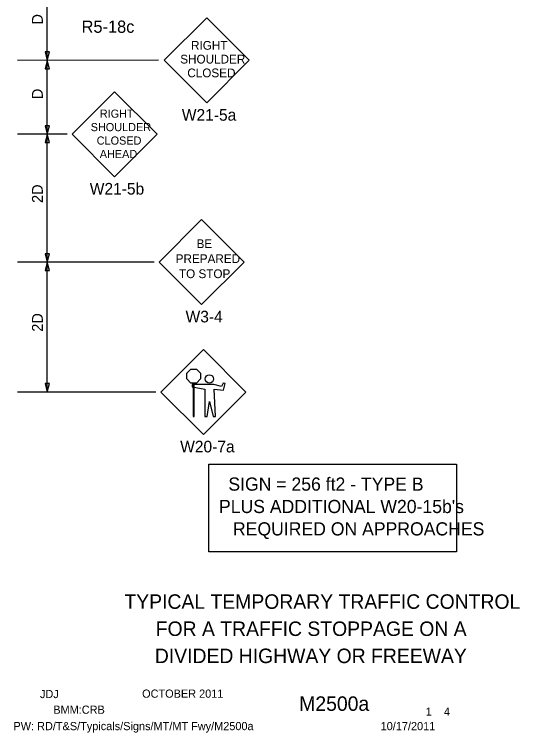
# Model space of a CAD drawing. Extents: x -1809 to 1554, y -1087 to 323.
# Drawn here: x -1380 to -996, y -949 to -403 of the extents above; entities that cross this region are included whole.
import ezdxf

# ---------------------------------------------------------------- set-up
doc = ezdxf.new("R2010")
doc.units = 0
for name, color, linetype in [('BORDER_SIGNAL_WO', 7, 'Continuous'), ('SCRATCH_LEVEL_C', 7, 'Continuous'), ('TRAFFIC_SIGNS_PR', 7, 'Continuous'), ('TYPICAL_TEXT_DIMEN_PR', 7, 'Continuous')]:
    doc.layers.add(name, color=color, linetype=linetype)

msp = doc.modelspace()

# ---------------------------------------------------------------- linework, layer by layer
at = {"layer": 'SCRATCH_LEVEL_C'}
msp.add_lwpolyline([(-1232.08, -744.7), (-1043.79, -744.7), (-1043.79, -811.2), (-1232.08, -811.2)], close=True, dxfattribs=at)
at = {"layer": 'TRAFFIC_SIGNS_PR'}
for p, q in [((-1233.59, -405.87), (-1265.83, -438.12)), ((-1201.35, -438.12), (-1233.59, -405.87)), ((-1265.83, -438.12), (-1233.59, -470.36)), ((-1233.59, -470.36), (-1201.35, -438.12)), ((-1303.55, -461.96), (-1335.79, -494.2)), ((-1271.3, -494.2), (-1303.55, -461.96)), ((-1335.79, -494.2), (-1303.55, -526.45)), ((-1303.55, -526.45), (-1271.3, -494.2)), ((-1237.46, -559.02), (-1269.7, -591.26)), ((-1205.21, -591.26), (-1237.46, -559.02)), ((-1269.7, -591.26), (-1237.46, -623.5)), ((-1237.46, -623.5), (-1205.21, -591.26)), ((-1236.11, -657.7), (-1268.35, -689.95)), ((-1203.86, -689.95), (-1236.11, -657.7)), ((-1268.35, -689.95), (-1236.11, -722.19)), ((-1236.11, -722.19), (-1203.86, -689.95))]:
    msp.add_line(p, q, dxfattribs=at)
for points in [[(-1245.65, -672.57), (-1241.29, -672.57), (-1238.21, -675.65), (-1238.21, -680.01), (-1241.29, -683.1), (-1245.65, -683.1), (-1248.74, -680.02), (-1248.74, -675.65)], [(-1228.17, -684.34), (-1244.59, -684.34), (-1244.59, -686.12), (-1235.13, -687.85), (-1235.13, -708.51), (-1233.35, -708.51), (-1231.56, -697.11), (-1228.71, -708.51), (-1226.93, -708.51), (-1228, -687.85), (-1220.88, -688.56), (-1219.45, -683.57), (-1221.18, -683.14), (-1222.25, -685.63)], [(-1243.83, -683.1), (-1243.83, -708.49), (-1243.12, -708.49), (-1243.12, -683.1)]]:
    msp.add_lwpolyline(points, close=True, dxfattribs=at)
msp.add_circle((-1231.59, -680.04), 3.21, dxfattribs=at)
at = {"layer": 'TYPICAL_TEXT_DIMEN_PR'}
for p, q in [((-1354.72, -438.17), (-1354.72, -382.13)), ((-1354.72, -431.79), (-1356.42, -431.79)), ((-1356.42, -431.79), (-1354.72, -438.19)), ((-1354.72, -438.19), (-1353.03, -431.79)), ((-1353.03, -431.79), (-1354.72, -431.79)), ((-1270.18, -438.12), (-1377.28, -438.21)), ((-1354.72, -438.19), (-1356.42, -444.59)), ((-1354.72, -493.97), (-1354.72, -438.17)), ((-1353.03, -444.59), (-1354.72, -438.19)), ((-1356.42, -444.59), (-1354.72, -444.59)), ((-1354.72, -444.59), (-1353.03, -444.59)), ((-1354.72, -487.74), (-1356.42, -487.74)), ((-1356.42, -487.74), (-1354.72, -494.14)), ((-1354.72, -494.14), (-1353.03, -487.74)), ((-1353.03, -487.74), (-1354.72, -487.74)), ((-1339.58, -494.19), (-1377.28, -494.07)), ((-1354.72, -494.14), (-1356.42, -500.54)), ((-1354.72, -591.29), (-1354.72, -493.97)), ((-1353.03, -500.54), (-1354.72, -494.14)), ((-1356.42, -500.54), (-1354.72, -500.54)), ((-1354.72, -500.54), (-1353.03, -500.54)), ((-1354.72, -584.98), (-1356.42, -584.98)), ((-1356.42, -584.98), (-1354.72, -591.38)), ((-1354.72, -591.38), (-1353.03, -584.98)), ((-1353.03, -584.98), (-1354.72, -584.98)), ((-1273.58, -591.26), (-1377.28, -591.41)), ((-1354.72, -591.38), (-1356.42, -597.79)), ((-1354.72, -689.87), (-1354.72, -591.29)), ((-1353.03, -597.79), (-1354.72, -591.38)), ((-1356.42, -597.79), (-1354.72, -597.79)), ((-1354.72, -597.79), (-1353.03, -597.79)), ((-1354.72, -683.54), (-1356.42, -683.54)), ((-1356.42, -683.54), (-1354.72, -689.95)), ((-1354.72, -689.95), (-1353.03, -683.54)), ((-1353.03, -683.54), (-1354.72, -683.54)), ((-1272.37, -689.95), (-1377.28, -689.95))]:
    msp.add_line(p, q, dxfattribs=at)

# ---------------------------------------------------------------- texts
at = {"layer": 'BORDER_SIGNAL_WO'}
for s, height, p in [(' TYPICAL TEMPORARY TRAFFIC CONTROL', 11, (-1300.21, -854.53)), ('FOR A TRAFFIC STOPPAGE ON A', 11, (-1272.34, -875.13)), ('DIVIDED HIGHWAY OR FREEWAY ', 11, (-1273, -895.73)), ('    OCTOBER 2011', 6.2, (-1291.88, -922.02)), ('JDJ         ', 6.2, (-1360.28, -922.3)), ('    M2500a   ', 11, (-1179.65, -931.98)), ('BMM:CRB', 6.2, (-1350.15, -934.19)), (' 1    4 ', 6.2, (-1069.51, -935.66)), ('PW: RD/T&S/Typicals/Signs/MT/MT Fwy/M2500a       ', 6.2, (-1380.41, -946.65)), ('10/17/2011', 6.2, (-1101.46, -946.65))]:
    msp.add_text(s, height=height, dxfattribs=at).set_placement(p)
at = {"layer": 'SCRATCH_LEVEL_C'}
for s, p in [('SIGN = 256 ft2 - TYPE B', (-1217.14, -764.83)), ("PLUS ADDITIONAL W20-15b's", (-1224.27, -781.83)), ('REQUIRED ON APPROACHES', (-1213.63, -798.83))]:
    msp.add_text(s, height=10, dxfattribs=at).set_placement(p)
at = {"layer": 'TRAFFIC_SIGNS_PR'}
for s, height, p in [('R5-18c', 9.3, (-1328.63, -417.23)), ('RIGHT', 6.65, (-1245.5, -430.09)), ('SHOULDER', 6.65, (-1253.69, -440.54)), ('CLOSED', 6.65, (-1248.32, -450.99)), ('RIGHT', 6.175, (-1314.79, -481.69)), ('W21-5a', 8.835, (-1252.49, -483.95)), ('SHOULDER', 6.175, (-1321.73, -491.9)), ('CLOSED', 6.175, (-1317.15, -502.12)), ('AHEAD', 6.175, (-1314.85, -512.33)), ('W21-5b', 8.835, (-1322.45, -540.03)), ('BE', 6.65, (-1241.28, -580.66)), ('PREPARED', 6.65, (-1257.15, -592.06)), ('TO STOP', 6.65, (-1254.68, -603.46)), ('W3-4', 8.835, (-1249.65, -637.09)), ('W20-7a', 8.835, (-1253.76, -735.77))]:
    msp.add_text(s, height=height, dxfattribs=at).set_placement(p)
at = {"layer": 'TYPICAL_TEXT_DIMEN_PR'}
for s, p in [('D', (-1358.09, -410.96)), ('D', (-1358.09, -467.6)), ('2D', (-1358.09, -546.41)), ('2D', (-1358.09, -644.16))]:
    msp.add_text(s, height=8.25, rotation=90, dxfattribs=at).set_placement(p)

doc.saveas('drawing.dxf')
